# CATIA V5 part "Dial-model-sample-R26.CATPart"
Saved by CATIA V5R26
Part number: Dial-model-sample⇨ 3d-raku.com
Description:  COPYRIGHT 3Draku
Bounding box of the stored display mesh (mm): x -29.1 to 56.569, y -79.1 to -20.9, z -46.569 to 20
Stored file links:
  C:\Users\ina\OneDrive\03-etc\回転配置-No\Dial-model-sample.CATPart
  C:\Users\ina\OneDrive\03-etc\回転配置-No\Dial-001.CATPart
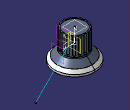
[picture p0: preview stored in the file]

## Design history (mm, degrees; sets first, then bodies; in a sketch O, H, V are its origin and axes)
Set1 "knob基準"
  Sketch1 on Plane7, origin (0, -50, 0), H (1, 0, 0), V (0, 0, 1)
    line L1 (4.0463, 5.9537) -> (56.5685, -46.5685)
    point P2 (56.5685, -46.5685)
    axis line L2 (0, 17.3095) -> (0, -13.3383)
    point P3 (0, 17.3095)
    construction line L3 (0, 10) -> (-2.9937, 10)
    point P5 (0, 10)
    angle L1 L2 = 45
    distance H L3 = 10
    distance P5 P2 = 80
    coincidence: P3 V, P5 L1, P5 L2
    vertical: L2 V
    horizontal: L3 H
  Plane1: type Offset, RefPlane Plane8, Offset 25
  Plane2: type Offset, RefPlane Plane8, Offset 17
  Plane3: type Offset, RefPlane Plane6, Offset 20
  Plane4: type OffsetPt, RefPlane Plane6, RefPoint Intersect1
  Intersect1: ToIntersect1 Sketch1, ToIntersect2 Plane2
  Plane5: type Offset, RefPlane Plane4, Offset 2
Set2 "基準"
  Point1 "中心点": (0, -50, 0)
  AxisSystem1: origin (0, -50, 0), X (0, -1, 0), Y (1, 0, 0), Z (0, 0, 1)
  Plane6 "XY平面": type OffsetPt, RefPlane XY plane of AxisSystem1, RefPoint Point1
  Plane7 "YZ平面": type OffsetPt, RefPlane YZ plane of AxisSystem1, RefPoint Point1
  Plane8 "ZX平面": type OffsetPt, RefPlane ZX plane of AxisSystem1, RefPoint Point1
  Line1: type PtDir, RefPoint Point1, Direction Plane8, Start 0, End 20
  Line2: type PtDir, RefPoint Point1, Direction Plane6, Start 0, End 20
Body1 (main body)
Body2 "knob"
  Body3 "knob"
    Sketch2 on Plane7, origin (0, -50, 0), H (1, 0, 0), V (0, 0, 1)
      line L1 (17, -7) -> (25, -15)
      line L2 (25, -15) -> (25, -17)
      line L3 (25, -17) -> (0, -17)
      reference projected line E1 (4.0463, 5.9537) -> (17.6777, -7.6777) from Sketch1
      axis line L4 (0, 25.1664) -> (0, -13.215)
      point P3 (0, 25.1664)
      point P4 (0, 10)
      line L5 (17, 20) -> (17, -7)
      line L6 (15, 20) -> (17, 20)
      point P7 (0, -17)
      point P9 (0, 19.5)
      line L7 (0, 19.5) -> (15, 19.5)
      line L8 (15, 19.5) -> (15, 20)
      reference intersected line E2 through (0, 20) direction (-1, 0) from Plane3
      reference intersected line E3 through (25, 0) direction (0, 1) from Plane1
      reference intersected line E4 through (17, 0) direction (0, 1) from Plane2
      length L2 = 2
      distance L7 L6 = 0.5
      distance L8 L5 = 2
      vertical: L2 V, L4 V, L5 V, L8 V
      horizontal: L3 H, L6 H, L7 H
      coincidence: L1 E1, P3 V, L1 P4, L4 P4, P7 L4, P9 L4, L6 E2, L2 E3, E4 L5
    Shaft1: profile Sketch2, axis Sketch2.L4, angle 90, second angle 90
    Fillet1: radius 2, on edge [face of Shaft1 from Sketch2.L5 | face of Shaft1 from Sketch2.L1]
    Mirror1: of the body so far, about face of Shaft1
    Body4
      Sketch3 on Plane3, origin (0, -50, 20), H (0, -1, 0), V (1, 0, 0)
        circle A1 centre (0, 17.5) radius 1.5
        point P1 (0, 17.5)
        reference intersected line E1 through (0, 17) direction (-1, 0) from Plane2
        radius A1 = 1.5
        distance E1 P1 = 0.5
        coincidence: P1 V
      Pad1: profile Sketch3, direction (0, 0, -1), up to Plane5
      Fillet2: radius 1, on edge [end face of Pad1 | face of Pad1 from Sketch3.A1]
      CircPattern1: of the body so far, instances 17, angular step 21.1765 {= 360.0*1 deg/CircPattern1.AngularNumber}, axis from edge [ZX plane of AxisSystem1 | YZ plane of AxisSystem1]
    Remove1: tool Body4
  Add1: tool Body3
Body5 "Ring"
  Sketch4 on Plane7, origin (0, -50, 0), H (1, 0, 0), V (0, 0, 1)
    axis line L1 (0, 25.1664) -> (0, -15.0675)
    point P1 (0, 25.1664)
    point P3 (0, 10)
    line L2 (25.1, -15.1) -> (29.1, -19.1)
    line L3 (29.1, -19.1) -> (29.1, -22.1)
    line L4 (29.1, -22.1) -> (0, -22.1)
    point P6 (0, -22.1)
    reference projected line E1 (17.8591, -7.8591) -> (10.087, -0.087) from Sketch2.L1
    point P7 (0, -17)
    line L5 (0, -17) -> (25.1, -17)
    line L6 (25.1, -17) -> (25.1, -15.1)
    reference projected line E2 (25, -17) -> (25, -15) from Sketch2.L2
    reference projected line E3 (0, -17) -> (25, -17) from Sketch2.L3
    distance E2 L6 = 0.1
    distance L3 L6 = 4
    length L3 = 3
    coincidence: P1 V, L1 P3, P6 L1, E1 L2, P7 L1, E3 L5
    vertical: L1 V, L3 V, L6 V
    horizontal: L4 H, L5 H
  Shaft2: profile Sketch4, axis Sketch4.L1, angle 90, second angle 90
  Mirror2: of Shaft2, about face of Shaft2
